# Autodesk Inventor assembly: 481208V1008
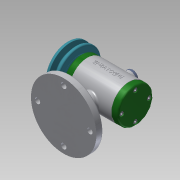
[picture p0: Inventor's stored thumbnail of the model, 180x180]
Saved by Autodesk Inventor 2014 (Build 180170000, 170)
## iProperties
Created: 2018-12
Part Number: 481208V1008
Document SubType Name: Assembly
Designer: 601-05
Author: 601-05
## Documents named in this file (15)
- C:\Users\601-05\Desktop\481208V1008.iam
- C:\Users\601-05\Desktop\481208V1008.ipt
- C:\Users\601-05\Desktop\481208V1008\V벨트풀리.ipt
- C:\Users\601-05\Desktop\481208V1008\고무캡.ipt
- C:\Users\601-05\Desktop\481208V1008\너트 M8.ipt
- 너트 M8.ipt
- C:\Users\601-05\Desktop\481208V1008\뒤커버.ipt
- C:\Users\601-05\Desktop\481208V1008\베어링 15 x 32 x 9.ipt
- C:\Users\601-05\Desktop\481208V1008\볼트 M4 x 12.ipt
- C:\Users\601-05\Desktop\481208V1008\스프링와셔 8.ipt
- C:\Users\601-05\Desktop\481208V1008\앞커버.ipt
- C:\Users\601-05\Desktop\481208V1008\오일 실 15 25 7.ipt
- C:\Users\601-05\Desktop\481208V1008\와셔 8x17.ipt
- C:\Users\601-05\Desktop\481208V1008\축.ipt
- C:\Users\601-05\Desktop\481208V1008\키 3 x 3 x 12.ipt
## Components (3 placed, 3 different names)
1. 481208V1008:1
2. V벨트풀리:1
3. 고무캡:1
